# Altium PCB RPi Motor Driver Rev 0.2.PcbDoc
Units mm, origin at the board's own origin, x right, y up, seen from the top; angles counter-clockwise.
Board outline 65.25 x 56.75 mm, 2 copper layers (Top, Bottom); 42 components, 51 nets, 197 pads, 38 vias.
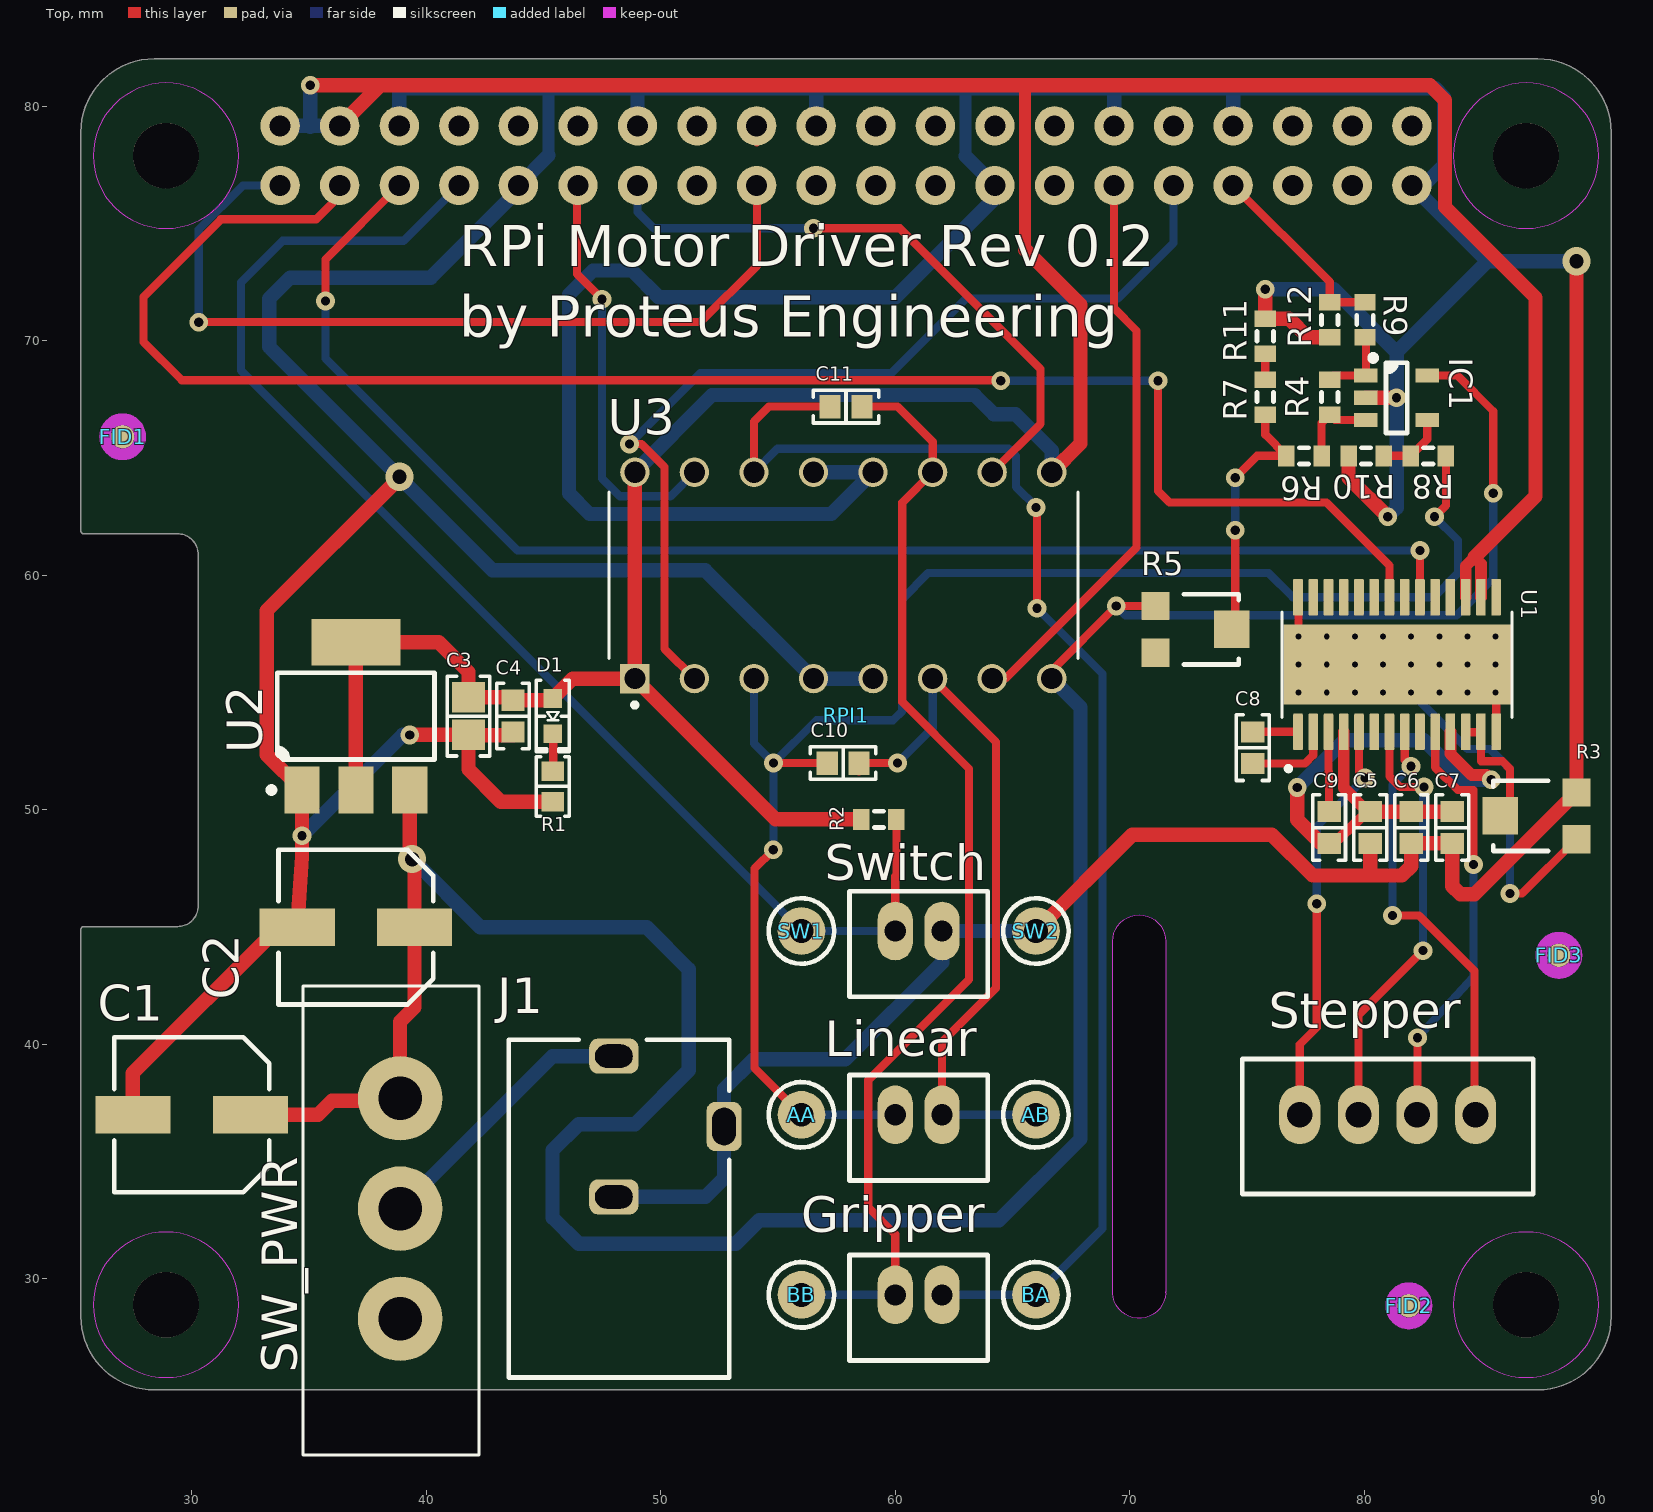
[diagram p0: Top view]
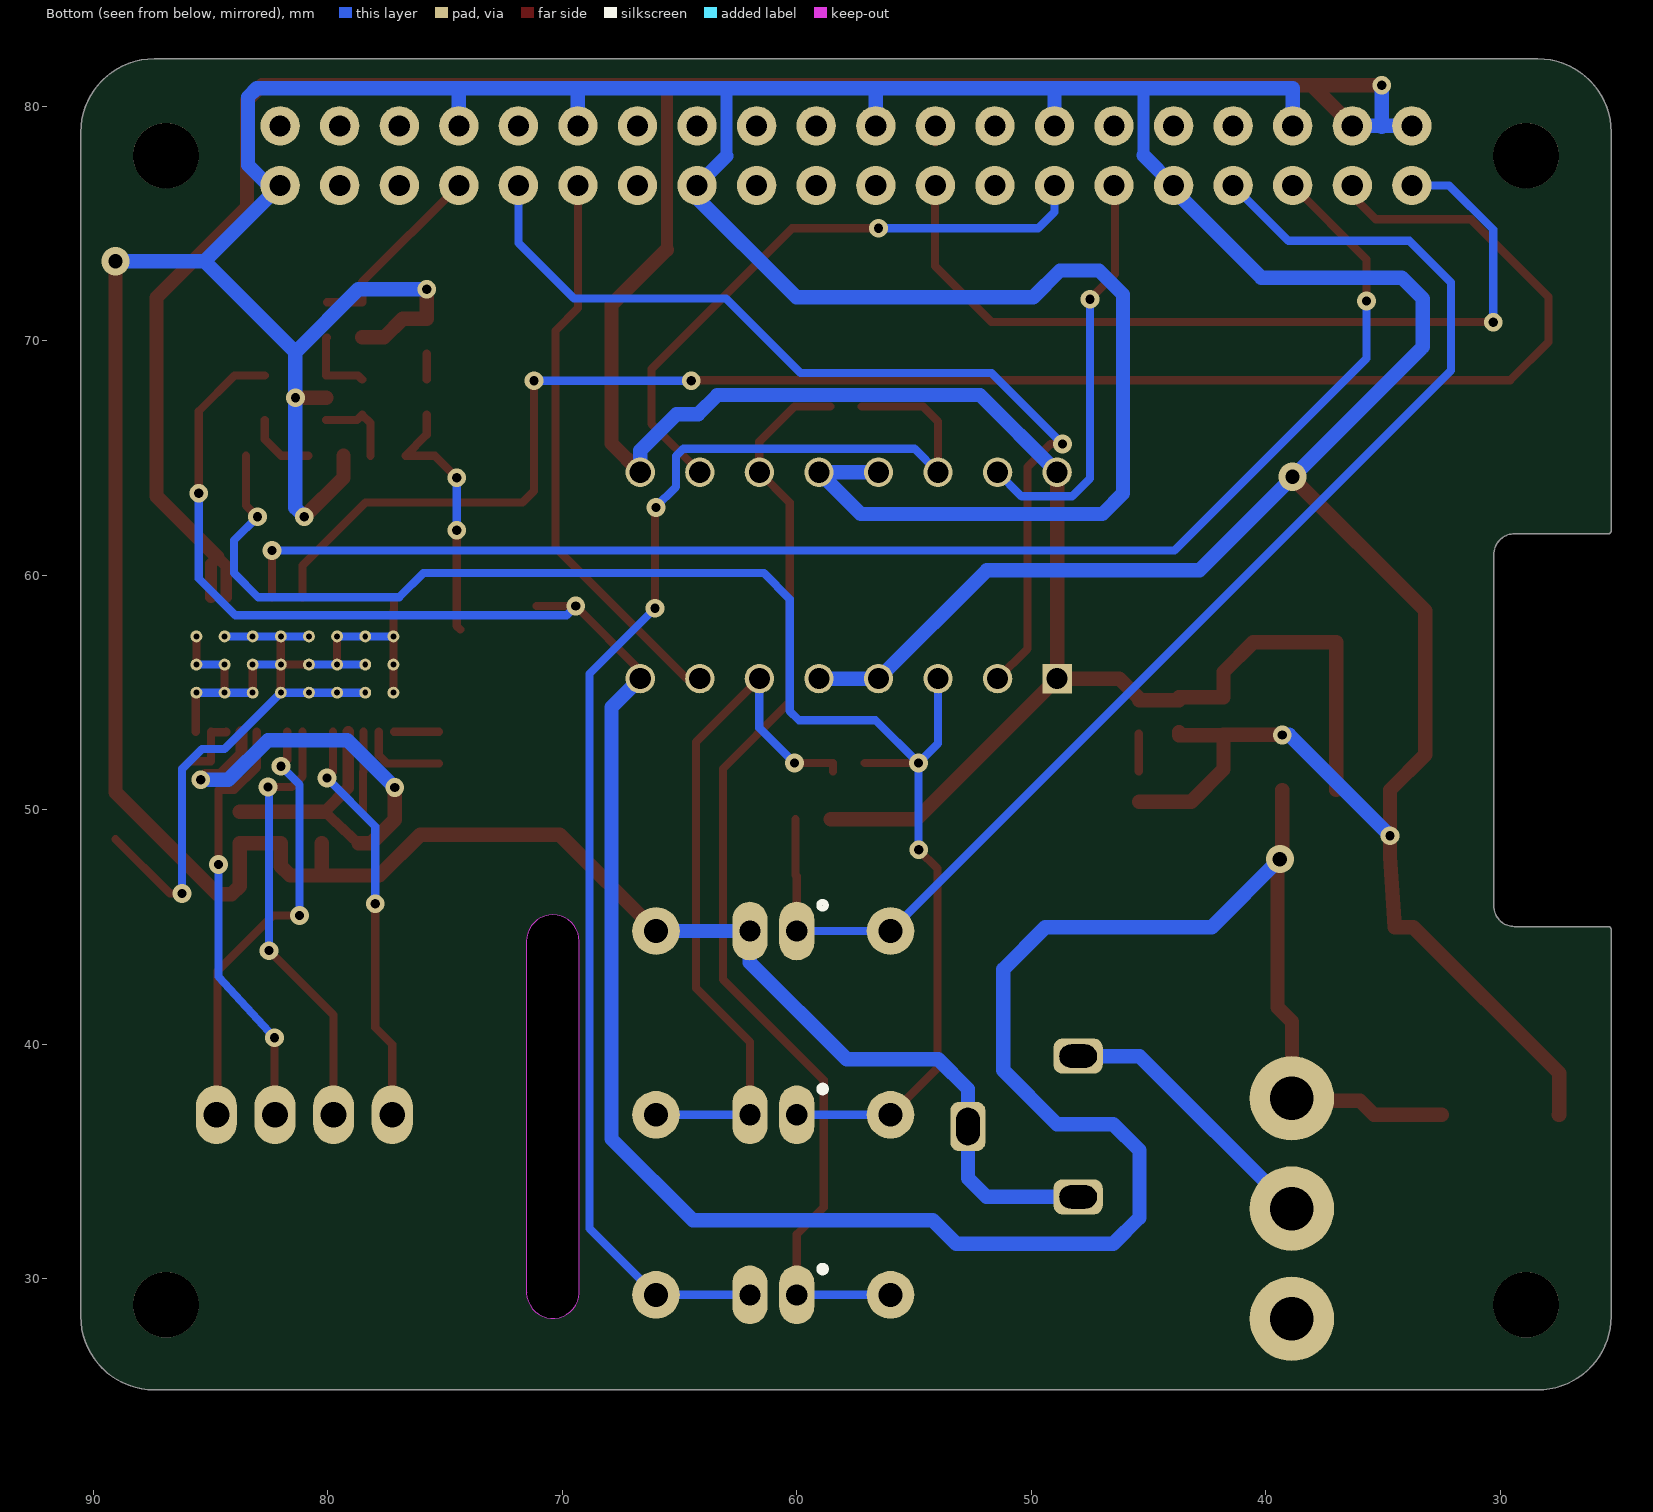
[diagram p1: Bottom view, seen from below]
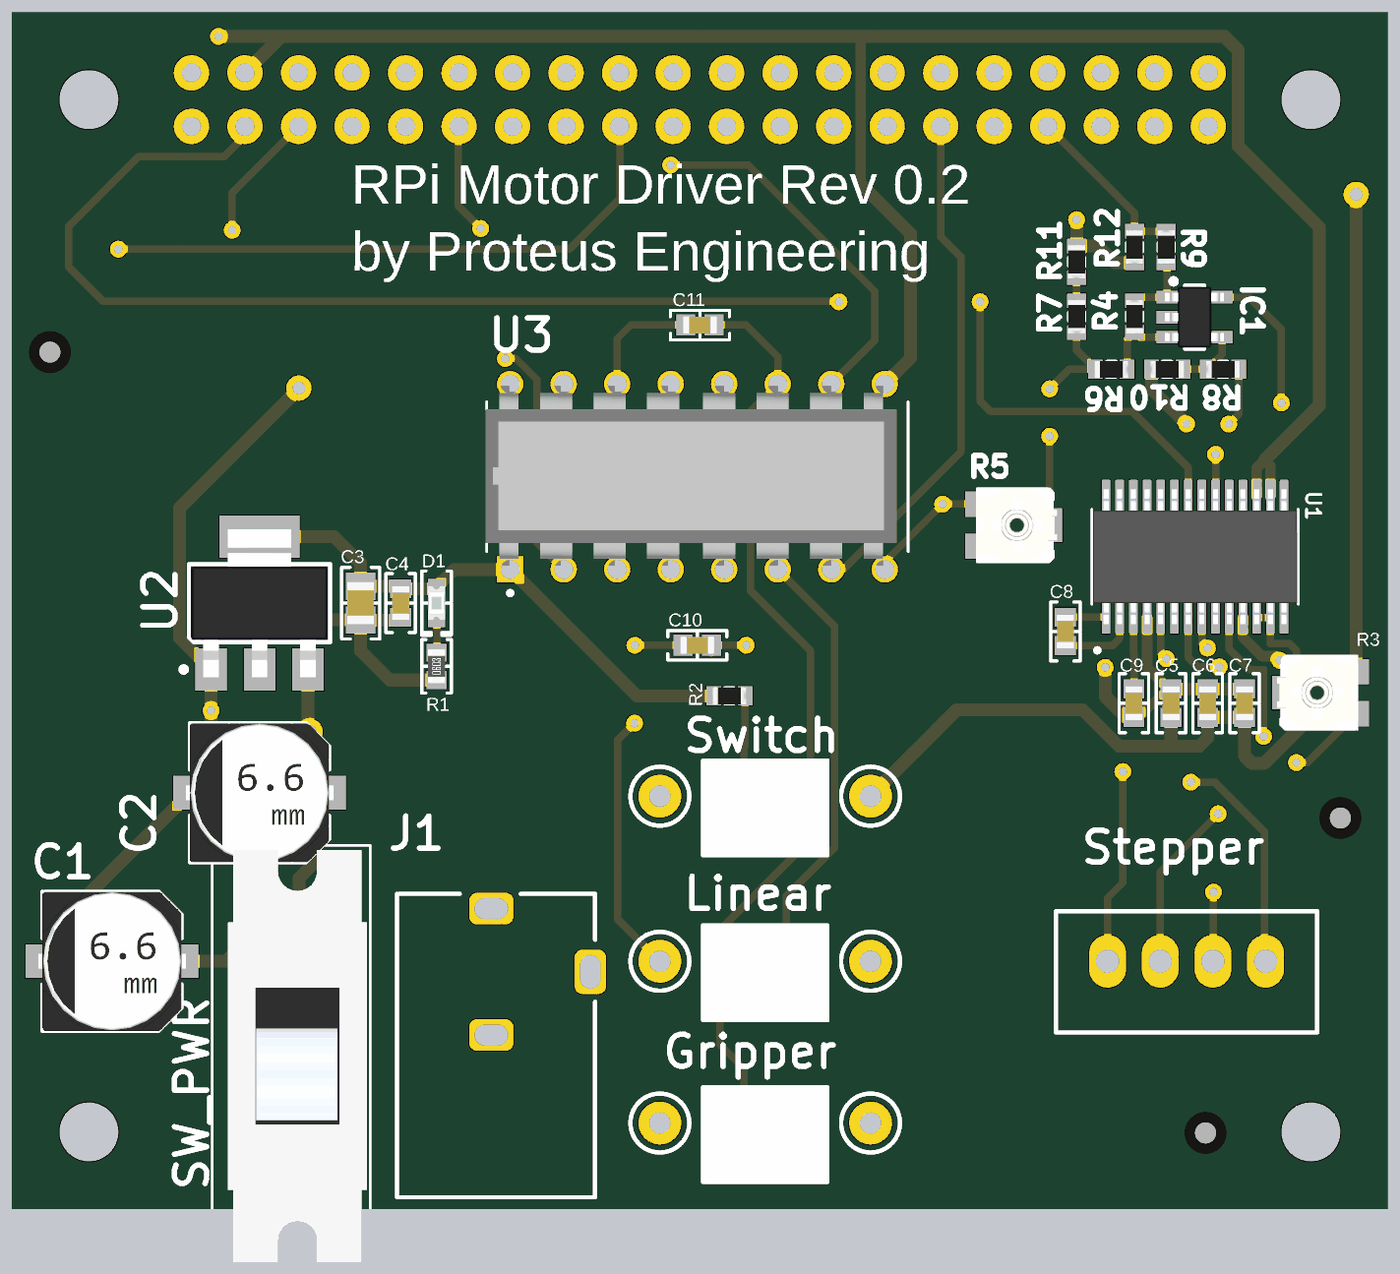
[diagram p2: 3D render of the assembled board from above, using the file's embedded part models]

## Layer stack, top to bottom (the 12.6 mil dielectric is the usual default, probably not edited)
Top Solder: solder mask 0.0102, Solder Resist, Dk 3.5
Top: signal copper 0.035
Dielectric 1: dielectric 0.32, FR-4, Dk 4.8
Bottom: signal copper 0.035
Bottom Solder: solder mask 0.0102, Solder Resist, Dk 3.5

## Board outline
25.273,28.4 25.273,44.9 cw(c25.4,44.9) 25.401,45.027 29.4,45.027 ccw(c29.4,45.9) 30.273,45.9 30.273,60.9 ccw(c29.4,60.9) 29.4,61.773 25.4,61.773 cw(c25.4,61.9) 25.273,61.9 25.273,78.9 cw(c28.4,78.9) 28.4,82.027 87.4,82.027 cw(c87.4,78.9) 90.528,78.9 90.528,28.4 cw(c87.4,28.4) 87.4,25.273 28.4,25.273 cw(c28.4,28.4)
cut-out: 69.277,29.432 cw(c69.4,29.464) 69.273,29.464 69.273,44.4 cw(c70.4,44.4) 71.527,44.4 71.527,29.464 cw(c71.4,29.464) 71.523,29.432 cw(c71.4,29.4) 71.527,29.4 cw(c71.4,29.4) 71.527,29.394 cw(c70.4,29.449) 69.273,29.394 cw(c69.4,29.4)

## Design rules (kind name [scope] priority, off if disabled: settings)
Clearance "Clearance (Same Net)" [All] p1: gap=0.203 ignorepadtopadclearanceinfootprint=FALSE
Clearance [All] p2: gap=0.152 ignorepadtopadclearanceinfootprint=FALSE
ComponentClearance [All] p1 off: gap=0.254 collisioncheckmode=3 verticalgap=0.254 showdistances=FALSE
HoleSize [All] p1: absolutevalues=TRUE maxlimit=2540 minlimit=0.254 maxpercent=80.000 minpercent=20.000
HoleToHoleClearance mdDrill [All] p1: gap=0.203 allowstackedmicrovias=TRUE
PasteMaskExpansion Expansion_SMDPaste_OFF [InPadClass('SMDPaste_OFF')] p1: expansion=0
PasteMaskExpansion mlMinCreamFrame [All] p2: expansion=0
PolygonConnect ThermalVias [IsVia] p1: connectstyle=Direct reliefconductorwidth=0.254 reliefentries=4 polygonreliefangle="90 Angle" airgapwidth=0.254
PolygonConnect [All] p2: connectstyle=Relief reliefconductorwidth=0.254 reliefentries=4 polygonreliefangle="90 Angle" airgapwidth=0.254
RoutingVias [All] p1: holewidth=0.394 width=0.8 viastyle="Through Hole" minholewidth=0.394 minwidth=0.8 maxholewidth=2.54 maxwidth=2.54
SolderMaskExpansion mlMinStopFrame [All] p1: expansion=0.051
Width [All] p1: maxlimit=0.7 minlimit=0.35 preferedwidth=0.35
26 further rules are at their usual default settings.

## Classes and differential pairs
pad class SMDPaste_OFF: FID1-1 FID2-1

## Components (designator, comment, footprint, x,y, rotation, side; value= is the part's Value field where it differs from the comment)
AA "TH_Testpoint_40mil" TH_Testpoint_40mil 56,37 r0 top
AB "TH_Testpoint_40mil" TH_Testpoint_40mil 66,37 r0 top
BA "TH_Testpoint_40mil" TH_Testpoint_40mil 66,29.322 r0 top
BB "TH_Testpoint_40mil" TH_Testpoint_40mil 56,29.322 r0 top
C1 "47µF" "CAP ALSMD 6.6MM H6.1MM" 30,37 r180 top
C2 "47µF" "CAP ALSMD 6.6MM H6.1MM" 37,45 r180 top
C3 "10µF" "CAP 0805_2012" 41.8,54 r90 top
C4 "0.1µF" "CAP 0603_1608" 43.7,54 r90 top
C5 "4.7µF" "CAP 0603_1608" 80.26,49.25 r90 top
C6 "0.1µF" "CAP 0603_1608" 82,49.25 r90 top
C7 "0.1µF" "CAP 0603_1608" 83.753,49.25 r90 top
C8 "0.01µF" "CAP 0603_1608" 75.25,52.655 r90 top
C9 "0.1µF" "CAP 0603_1608" 78.5,49.25 r90 top
C10 "0.1µF" "CAP 0603_1608" 57.775,52 r180 top
C11 "0.1µF" "CAP 0603_1608" 57.9,67.2 r180 top
D1 "Green" "LED 0603_1608 GREEN" 45.4,54 r270 top
FID1 "FIDUCIAL\"\"" FIDUCIAL_1MM 27.051,65.913 r0 top
FID2 "FIDUCIAL\"\"" FIDUCIAL_1MM 81.9,28.853 r0 top
FID3 "FIDUCIAL\"\"" FIDUCIAL_1MM 88.3,43.8 r0 top
Gripper "B2B-PH-K-S(LF)(SN)" "JST B2B-PH-K" 61,29.322 r0 top
IC1 "AD8615AUJZ-REEL" "ANALOG TSOT-23-5 UJ-5" 81.38,67.575 r0 top
Linear "B2B-PH-K-S(LF)(SN)" "JST B2B-PH-K" 61,37 r0 top
R1 "100 Ohms" "RES 0603_1608" 45.4,51 r90 top
R2 "Resistor 0603" 0603R 59.3,49.6 r180 top value=100k
R3 "10 kOhms" "POT BOURNS TRIMPOT TC33" 87.25,49.75 r90 top
R4 "Resistor 0603" 0603R 78.53,67.6 r270 top value=50k
R5 "200 Ohms" "POT BOURNS TRIMPOT TC33" 72.9,57.7 r270 top
R6 "Resistor 0603" 0603R 77.43,65.1 r180 top value=1k
R7 "Resistor 0603" 0603R 75.78,67.6 r90 top value=200
R8 "Resistor 0603" 0603R 82.73,65.1 r0 top value=1k
R9 "Resistor 0603" 0603R 80.03,70.9 r270 top value=470k
R10 "Resistor 0603" 0603R 80.08,65.1 r0 top value=50k
R11 "Resistor 0603" 0603R 75.78,70.2 r90 top value=470
R12 "Resistor 0603" 0603R 78.53,70.9 r90 top value=200k
RPI1 "RASPBERRYPI_BPLUS_HATSLOTS" PI_HAT_SLOTS 25.4,25.4 r0 top
SW1 "TH_Testpoint_40mil" TH_Testpoint_40mil 56,44.835 r0 top
SW2 "TH_Testpoint_40mil" TH_Testpoint_40mil 66,44.835 r0 top
SW_PWR "48ASSP3S1M2QBT" "SWITCH SLIDE SPDT 5A 125V" 36,33 r270 top
Switch "B2B-PH-K-S(LF)(SN)" "JST B2B-PH-K" 61,44.835 r0 top
U1 "DRV8825PWP" SOP65P640X120-29N 81.4,56.2 r90 top
U2 "NCP1117ST50T3G" "ON SEMI SOT-223 ST(318H)" 37,54 r90 top
U3 "L293D" DIP880W50P254L2000H510Q16 57.785,60 r90 top

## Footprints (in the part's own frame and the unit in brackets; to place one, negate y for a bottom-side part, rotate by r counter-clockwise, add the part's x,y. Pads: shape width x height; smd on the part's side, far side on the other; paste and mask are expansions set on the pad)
0603R [mm] "Resistor"
  rect 0.7x0.9 smd: 1(-0.75,0) 2(0.75,0)
  silkscreen extent -0.2,-0.35 0.2,0.35, body extent -0.8,-0.4 0.8,0.4, height 0.45
"ANALOG TSOT-23-5 UJ-5" [mm] "SOT23, 5-Leads, Body 2.90x1.60mm, Pitch 0.95mm, IPC Medium Density"
  rect 1x0.6 smd: 1(-1.31,0.95) 2(-1.31,0) 3(-1.31,-0.95) 4(1.31,-0.95) 5(1.31,0.95)
  silkscreen extent -1.12,-1.5 0.45,1.82, body extent -1.4,-1.45 1.4,1.45, height 1
"CAP 0603_1608" [mm] "Chip Capacitor, 2-Leads, Body 1.60x0.80mm, IPC Medium Density"
  rect 0.9x1 smd: 1(-0.675,0) 2(0.675,0)
  silkscreen extent -1.4,-0.7 1.4,0.7, body extent -0.8,-0.41 0.8,0.41, height 0.82
"CAP 0805_2012" [mm] "Chip Capacitor, 2-Leads, Body 2.00x1.20mm, IPC Medium Density"
  rect 1.3x1.4 smd: 1(-0.8,0) 2(0.8,0)
  silkscreen extent -1.7,-0.9 1.7,0.9, body extent -1,-0.64 1,0.64, height 1.26
"CAP ALSMD 6.6MM H6.1MM" [mm] "Aluminum Electrolytic Capacitor, Body 6.60x6.60x6.10mm, IPC Low Density"
  rect 3.2x1.6 smd: 1(-2.5,0) 2(2.5,0)
  silkscreen extent -3.3,-3.3 3.3,3.3, body extent -3.5,-3.3 3.5,3.3, height 6.1
DIP880W50P254L2000H510Q16 [mm]
  rect 1.25x1.25 hole 0.9: 1(-4.4,8.89)
  round 1.25 hole 0.9: 2(-4.4,6.35) 3(-4.4,3.81) 4(-4.4,1.27) 5(-4.4,-1.27) 6(-4.4,-3.81) 7(-4.4,-6.35) 8(-4.4,-8.89) 9(4.4,-8.89) 10(4.4,-6.35) 11(4.4,-3.81) 12(4.4,-1.27) 13(4.4,1.27) 14(4.4,3.81) 15(4.4,6.35) 16(4.4,8.89)
  silkscreen extent -5.62,-10 3.55,10, body extent -4.23,-9.45 4.3,10.05, height 3.09
FIDUCIAL_1MM [mm] "FIDUCIAL_1MM"
  rrect100% 1x1 smd paste+0: 1(0,0)
  Top keep-out lines w0.5: -0.75,0 ccw(c0,0) 0,-0.75 ccw(c0,0) 0.75,0 ccw(c0,0) 0,0.75 ccw(c0,0) -0.75,0
"JST B2B-PH-K" [mm]
  oval 1.5x2.5 hole 0.9: 1(-1,0) 2(1,0)
  silkscreen extent -2.95,-2.8 2.95,1.7, body extent -2.95,-2.8 2.95,1.7, height 6
"LED 0603_1608 GREEN" [mm] "Chip Diode, 2-Leads, Body 1.60x0.80mm, IPC Medium Density"
  rect 0.8x0.8 smd: 1(-0.75,0) 2(0.75,0)
  silkscreen extent -1.52,-0.7 1.52,0.7, body extent -0.8,-0.4 0.8,0.4, height 0.53
"ON SEMI SOT-223 ST(318H)" [mm] "SOT223, 4-Leads, Body 6.50x7.00mm (avg), Pitch 2.30mm, IPC Medium Density"
  rect 2x1.5 smd: 1(-3.15,2.3) 2(-3.15,0) 3(-3.15,-2.3)
  rect 2x3.8 smd: 4(3.15,0)
  silkscreen extent -3.27,-3.35 1.85,3.72, body extent -3.52,-3.25 3.5,3.25, height 1.8
PI_HAT_SLOTS [mil] "PI_HAT_SLOTS"
  round 110.24 hole 110.24 unplated: 1(137.8,137.8) 1(137.8,2066.93) 1(2421.26,137.8) 1(2421.26,2066.93)
  round 66 / inner round 60 / far side round 66 hole 35.43: 1(329.53,2016.93) 2(329.53,2116.93) 3(429.53,2016.93) 4(429.53,2116.93) 5(529.53,2016.93) 6(529.53,2116.93) 7(629.53,2016.93) 8(629.53,2116.93) 9(729.53,2016.93) 10(729.53,2116.93) 11(829.53,2016.93) 12(829.53,2116.93) 13(929.53,2016.93) 14(929.53,2116.93) 15(1029.53,2016.93) 16(1029.53,2116.93) 17(1129.53,2016.93) 18(1129.53,2116.93) 19(1229.53,2016.93) 20(1229.53,2116.93) 21(1329.53,2016.93) 22(1329.53,2116.93) 23(1429.53,2016.93) 24(1429.53,2116.93) 25(1529.53,2016.93) 26(1529.53,2116.93) 27(1629.53,2016.93) 28(1629.53,2116.93) 29(1729.53,2016.93) 30(1729.53,2116.93) 31(1829.53,2016.93) 32(1829.53,2116.93) 33(1929.53,2016.93) 34(1929.53,2116.93) 35(2029.53,2016.93) 36(2029.53,2116.93) 37(2129.53,2016.93) 38(2129.53,2116.93) 39(2229.53,2016.93) 40(2229.53,2116.93)
  Top keep-out circle w0: c137.8,137.8 r122.05
  Top keep-out circle w0: c2421.26,137.8 r122.05
  Top keep-out circle w0: c137.8,2066.93 r122.05
  Top keep-out circle w0: c2421.26,2066.93 r122.05
"POT BOURNS TRIMPOT TC33" [mm] "Bourns Trimpot TC33X-1 - Open Frame 3mm x 3.8mm x 1.2mm"
  rect 1.2x1.2 smd: 1(-1,-1.8) 3(1,-1.8)
  rect 1.6x1.5 smd: 2(0,1.45)
  silkscreen extent -1.5,-0.6 1.5,1.75, body extent -1.8,-1.91 1.8,1.95, height 1.15
"RES 0603_1608" [mm] "Chip Resistor, 2-Leads, Body 1.60x0.80mm, IPC Medium Density"
  rect 0.85x0.95 smd: 1(-0.65,0) 2(0.65,0)
  silkscreen extent -1.27,-0.7 1.27,0.7, body extent -0.8,-0.4 0.8,0.4, height 0.45
SOP65P640X120-29N [mm]
  rrect25% 1.57x0.41 smd: 1(-2.87,4.225) 2(-2.87,3.575) 3(-2.87,2.925) 4(-2.87,2.275) 5(-2.87,1.625) 6(-2.87,0.975) 7(-2.87,0.325) 8(-2.87,-0.325) 9(-2.87,-0.975) 10(-2.87,-1.625) 11(-2.87,-2.275) 12(-2.87,-2.925) 13(-2.87,-3.575) 14(-2.87,-4.225) 15(2.87,-4.225) 16(2.87,-3.575) 17(2.87,-2.925) 18(2.87,-2.275) 19(2.87,-1.625) 20(2.87,-0.975) 21(2.87,-0.325) 22(2.87,0.325) 23(2.87,0.975) 24(2.87,1.625) 25(2.87,2.275) 26(2.87,2.925) 27(2.87,3.575) 28(2.87,4.225)
  rect 3.4x9.7 smd paste-6 mask+0: 29(0,0)
  round 0.508 hole 0.254: P1(-1.2,0.6) P2(0,0.6) P3(1.2,0.6) P4(-1.2,-0.6) P5(0,-0.6) P6(1.2,-0.6) P7(-1.2,-1.8) P8(0,-1.8) P9(1.2,-1.8) P16(-1.2,1.8) P17(0,1.8) P18(1.2,1.8)
  round 0.508 hole 0.254 mask+0: P10(-1.2,-3) P11(0,-3) P12(1.2,-3) P13(-1.2,-4.2) P14(0,-4.2) P15(1.2,-4.2) P19(-1.2,3) P20(0,3) P21(1.2,3) P22(-1.2,4.2) P23(0,4.2) P24(1.2,4.2)
  silkscreen extent -4.54,-4.9 2.25,4.9, body extent -3.2,-4.85 3.2,4.85, height 1.18
"SWITCH SLIDE SPDT 5A 125V" [mm]
  round 3.6 hole 1.85 paste+0 mask+0.102: 1(-4.7,2.885) 2(0,2.885) 3(4.7,2.885)
  silkscreen extent -9.5,-1.25 10.5,6.25, body extent -9.28,-0.5 10.28,6.1, height 11.41
TH_Testpoint_40mil [mil]
  round 80 hole 40 paste-40: 1(0,0)
  silkscreen extent -55,-55 55,55

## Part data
AA AB BA BB SW1 SW2: "TH Testpoint"
C1 C2: library part UCD1V470MCL1GS, "CAP ALUM 47UF 20% 35V SMD", Device Package="Radial, Can - SMD", Lifetime @ Temp.="2000 Hrs @ 105°C", Manufacturer=Nichicon, Operating Temperature="-55°C ~ 105°C", Part Number=EEE-FP1V470AP, Ratings=AEC-Q200, Ripple Current @ High Frequency="240mA @ 100kHz", Ripple Current @ Low Frequency="120mA @ 120Hz", Supplier Part Number 1=493-6426-1-ND, Tolerance=±20%, Voltage - Rated=35V
C3: library part C2012X5R1E106K085AC, "CAP CER 10UF 25V X5R 0805", Device Package="0805 (2012 Metric)", Manufacturer="TDK Corporation", Operating Temperature="-55°C ~ 85°C", Supplier Part Number 1=445-14387-1-ND, Temperature Coefficient=X5R, Tolerance=±10%, Voltage - Rated=25V
C4 C6 C7 C9 C10 C11: library part CGA3E2X7R1H104K080AE, "CAP CER 0.1UF 50V X7R 0603", Device Package="0603 (1608 Metric)", Manufacturer="TDK Corporation", Operating Temperature="-55°C ~ 125°C", Ratings=AEC-Q200, Supplier Part Number 1=445-15957-1-ND, Temperature Coefficient=X7R, Tolerance=±10%, Voltage - Rated=50V
C5: library part C1608X5R1V475M080AC, "CAP CER 4.7UF 35V X5R 0603", Device Package="0603 (1608 Metric)", Manufacturer="TDK Corporation", Operating Temperature="-55°C ~ 85°C", Supplier Part Number 1=445-9042-1-ND, Temperature Coefficient=X5R, Tolerance=±20%, Voltage - Rated=35V
C8: library part C0603C103KARACAUTO, "CAP CER 0.01UF 250V X7R 0603", Device Package="0603 (1608 Metric)", Manufacturer=KEMET, Operating Temperature="-55°C ~ 125°C", Ratings=AEC-Q200, Supplier Part Number 1=399-17960-1-ND, Temperature Coefficient=X7R, Tolerance=±10%, Voltage - Rated=250V
D1: library part APHD1608LCGCK, "LED GREEN CLEAR 1608 SMD", Current - Test=2mA, Device Package="0603 (1608 Metric)", Lens Color=Colorless, Manufacturer=Kingbright, Millicandela Rating=5mcd, Part Number=APT1608CGCK, Supplier Device Package=1608, Supplier Part Number 1=754-2031-1-ND, Voltage - Forward (Vf) (Typ)=1.9V
FID1 FID2 FID3: "Fiducial Alignment PointsVarious fiducial points for machine vision alignment."
Gripper Linear Switch: "CONN HEADER VERT 2POS 2MM", Current Rating (Amps)=2A, Insulation Color=Natural, Manufacturer="JST Sales America Inc.", Material Flammability Rating="UL94 V-0", Operating Temperature="-25°C ~ 85°C", Supplier Part Number 1=455-1704-ND, Voltage Rating=100V
IC1: "IC OPAMP GP 1 CIRCUIT TSOT23-5", Current - Input Bias=0.2pA, Current - Output / Channel=150mA, Current - Supply=1.7mA, Device Package="SOT-23-5 Thin, TSOT-23-5", Manufacturer="Analog Devices Inc.", Operating Temperature="-40°C ~ 125°C", Supplier Device Package=TSOT-23-5, Supplier Part Number 1=AD8615AUJZ-REELTR-ND, Voltage - Input Offset=23µV, Voltage - Supply, Single/Dual (±)="2.7V ~ 5.5V, ±1.35V ~ 2.75V"
R1: library part RNCS0603BKE100R, "RES 100 OHM 0.1% 1/16W 0603", Device Package="0603 (1608 Metric)", Manufacturer="Stackpole Electronics Inc", Operating Temperature="-55°C ~ 155°C", Power (Watts)="0.063W, 1/16W", Ratings=AEC-Q200, Supplier Device Package=0603, Supplier Part Number 1=RNCS0603BKE100RCT-ND, Temperature Coefficient=±25ppm/°C, Tolerance=±0.1%
R2 R4 R6 R7 R8 R9 R10 R11 R12: library part Resistor
R3: library part TC33X-2-103E, "TRIMMER 10K OHM 0.1W J LEAD TOP", Manufacturer="Bourns Inc.", Power (Watts)="0.1W, 1/10W", Resistive Material=Cermet, Supplier Part Number 1=TC33X-103ECT-ND, Temperature Coefficient=±250ppm/°C, Tolerance=±25%
R5: library part TC33X-2-201E, "TRIMMER 200 OHM 0.1W J LEAD TOP", Manufacturer="Bourns Inc.", Power (Watts)="0.1W, 1/10W", Resistive Material=Cermet, Supplier Part Number 1=TC33X-2-201ECT-ND, Temperature Coefficient=±250ppm/°C, Tolerance=±25%
SW_PWR: library part "SWITCH SLIDE SPDT 5A 125V", "SWITCH SLIDE SPDT 5A 125V"
U1: "Bipolar Motor Driver Power MOSFET Logic 28-HTSSOP", Package="HTSSOP-28 Texas Instruments"
U2: "IC REG LINEAR 5V 1A SOT223", Current - Output=1A, Current - Quiescent (Iq)=10mA, Device Package="TO-261-4, TO-261AA", Manufacturer="ON Semiconductor", Operating Temperature="0°C ~ 125°C", Supplier Device Package=SOT-223, Supplier Part Number 1=NCP1117ST50T3GOSCT-ND, Voltage - Input (Max)=20V, Voltage - Output (Min/Fixed)=5V, Voltage Dropout (Max)="1.2V @ 800mA"
U3: "Bipolar Motor Driver Parallel 16-PowerDIP", Package="SOIC-20 STMicroelectronics"

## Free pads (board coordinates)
  rrect50% 2.1x1.5 hole 1 slot 1.6 at 0 deg: 1(48,39.5) 2(48,33.5)
  oval 1.75x2.5 hole 1.1: 1(77.25,37) 2(79.75,37) 3(82.25,37) 4(84.75,37)
  rrect50% 1.5x2.1 hole 1 slot 1.6 at 90 deg: 3(52.7,36.5)

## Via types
v1: diameter 0.8, hole 0.394, Top to Bottom, 35 vias
v2: diameter 1.2, hole 0.61, Top to Bottom, 2 vias
v3: diameter 1.2, hole 0.6, Top to Bottom, 1 vias

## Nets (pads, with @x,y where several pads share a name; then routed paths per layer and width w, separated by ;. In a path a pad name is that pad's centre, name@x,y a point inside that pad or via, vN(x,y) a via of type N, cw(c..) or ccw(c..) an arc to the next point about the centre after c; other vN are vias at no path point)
5V: C3.2 C4.2 D1.1 R2.2 RPI1.2 RPI1.4 U1.16 U1.17 U2.2 U2.4 U3.1 U3.9 U3.16 | length 161.7
  Top w0.5: 65.532,73.889 65.532,80.899 ; U1.17 84.325,60.403 84.7,60.778 84.975,60.503 U1.16
  Top w0.61: v1(35.052,80.899) 38.039,80.899 ; RPI1.4 38.039,80.899 ; U2.2 37,53.975 U2.4 40.53,57.15 41.8,55.88 C3.2 43.7,54.8 C4.2 45.4,54.675 D1.1 46.25,55.6 U3.1 ; U3.16 U3.1 ; R2.2 54.895,49.6 U3.1 ; 65.532,73.889 65.557,73.889 67.9,71.546 67.9,65.625 U3.9 ; 65.557,80.9 65.532,80.899 ; 84.7,60.778 87.3,63.378 87.3,71.847 83.439,75.708 83.439,80.264 82.804,80.899 65.532,80.899 ; 38.039,80.899 65.532,80.899
  Bottom w0.61: RPI1.2 35.052,79.17 ; v1(35.052,80.899) 35.052,79.17 ; RPI1.4 35.099,79.17 ; U3.16 52.186,67.691 63.384,67.691 64.207,66.868 65.132,66.868 66.675,65.325 U3.9 ; 35.052,79.17 35.052,79.123 35.099,79.17 ; 35.052,79.17 35.099,79.17
12V: C1.1 C2.1 IC1.5 R5.1 SW_PWR.1 U2.3 U3.8 | length 126.4
  Top w0.35: U3.8@66.675,55.951 v1(69.424,58.7) R5.1 ; IC1.5 83.975,68.525 85.5,67 v1(85.5,63.5)
  Top w0.61: C1.1 35.382,37 35.982,37.6 38.885,37.6 38.885,40.97 39.5,41.585 C2.1 39.5,47.803 39.3,48.003 U2.3
  Bottom w0.35: v1(69.424,58.7) 69.824,58.3 83.93,58.3 85.5,59.87 v1(85.5,63.5)
  Bottom w0.61: v2(39.4,47.903) 42.303,45 49.4,45 51.2,43.2 51.2,38.9 48.9,36.6 46.5,36.6 45.385,35.485 45.385,32.615 46.5,31.5 53.2,31.5 54.2,32.5 64.428,32.5 67.9,35.972 67.9,54.375 U3.8
A1: pad.1@77.25,37 U1.5 | length 17.6
  Top w0.35: pad.1@77.25,37 77.25,40 77.975,40.725 v1(77.975,46.004) ; U1.5 79.775,51.619 v1(80.035,51.359)
  Bottom w0.35: v1(77.975,46.004) 77.975,49.298 v1(80.035,51.359)
A2: pad.2@79.75,37 U1.7 | length 19.8
  Top w0.35: pad.2@79.975,36 79.75,36.225 79.75,37 79.75,41.25 v1(82.5,44) ; U1.7 81.075,51.435 81.532,50.978 v1(82.55,50.978)
  Bottom w0.35: v1(82.5,44) 82.5,50.928 v1(82.55,50.978)
B1: pad.3@82.25,37 U1.10 | length 18.3
  Top w0.35: pad.3@82.275,37 v1(82.275,40.283) ; U1.10 83.025,51.816 83.991,50.85 84.658,50.85 v1(84.658,47.676)
  Bottom w0.35: v1(82.275,40.283) 84.658,42.891 v1(84.658,47.676)
B2: pad.4 U1.8 | length 18.9
  Top w0.35: v1(81.2,45.5) 82.338,45.5 84.7,43.138 pad.4@84.7,37 ; U1.8 81.725,52.133 v1(81.991,51.867)
  Bottom w0.35: v1(81.2,45.5) 81.2,51.076 v1(81.991,51.867)
EECLK: RPI1.28 | length 0.2
  Top w0.35: RPI1.28@66.79,79.006 RPI1.28
EEDATA: RPI1.27
GND: C1.2 C2.2 C3.1 C4.1 C5.1 C6.1 C7.1 IC1.2 pad.2@48,33.5 pad.3@52.7,36.5 R1.1 R3.3 R10.1 R11.2 R12.1 RPI1.6 RPI1.9 RPI1.14 RPI1.20 RPI1.25 RPI1.30 RPI1.34 RPI1.39 SW2.1 Switch.2 U2.1 U3.4 U3.5 U3.12 U3.13 | length 327.2
  Top w0.61: C1.2 27.483,37 27.483,38.777 33.706,45 C2.2 34.7,48.003 U2.1 33.2,52.35 33.2,58.5 v3@38.887,64.187 ; v1@39.281,53.2 C3.1 C3.1@41.8,53.188 ; C4.1 43.7,53.188 C3.1@41.8,53.188 ; R1.1 43.18,50.35 41.8,51.73 C3.1@41.8,53.188 ; SW2.1 70.111,48.946 76.054,48.946 77.8,47.2 80.3,47.2 ; RPI1.34@74.41,78.752 RPI1.34 ; v1(75.78,72.2) R11.2 76.8,70.95 77.6,70.15 R12.1 ; R10.1 79.33,64.17 v1(81,62.5) ; IC1.2 v1(81.38,67.575) ; C5.1 80.26,47.24 80.3,47.2 ; v2(89.05,73.4) R3.3 84.7,46.4 84.1,46.4 83.753,46.747 C7.1 C6.1 82,47.6 81.6,47.2 80.3,47.2
  Bottom w0.35: 33.3,69.748 33.4,69.648
  Bottom w0.5: 45.212,77.912 45.212,80.645 ; 62.992,77.888 62.992,80.772
  Bottom w0.61: 33.3,69.748 33.3,71.8 34.2,72.7 40.188,72.7 43.93,76.442 RPI1.9 45.212,77.912 ; 33.4,69.648 42.824,60.223 51.892,60.223 U3.4 U3.5 ; v1(34.7,48.9) 39,53.2 v1(39.3,53.2) ; RPI1.6 38.85,80.772 45.339,80.772 ; 45.212,80.645 45.339,80.772 ; pad.2@48,33.5 51.91,33.5 52.7,34.29 52.7,36.5 52.7,38.1 53.97,39.37 57.872,39.37 62,43.497 Switch.2 63.983,44.835 SW2.1 ; RPI1.14 49.01,80.772 ; U3.13 U3.12 57.273,62.618 46.967,62.618 46.085,63.5 46.085,71.977 47.107,73 48.776,73 49.919,71.857 60.009,71.857 64.516,76.364 RPI1.25 62.992,77.888 ; RPI1.20 56.63,80.772 ; RPI1.30 69.342,79.17 69.342,80.772 ; RPI1.34 74.41,80.772 ; v1(75.78,72.2) 78.7,72.2 81.38,69.52 ; v1(81,62.5) 81.38,62.88 v1(81.38,67.575) 81.38,69.52 ; v2(89.05,73.4) 85.26,73.4 ; 45.339,80.772 49.01,80.772 ; 49.01,80.772 56.63,80.772 ; 56.63,80.772 62.992,80.772 69.342,80.772 ; 69.342,80.772 74.41,80.772 ; 74.41,80.772 83.028,80.772 83.4,80.4 83.4,77.5 82.53,76.63 RPI1.39 85.26,73.4 ; 81.38,69.52 85.26,73.4
  other v3: 38.866,64.208
GPIO12: RPI1.32
GPIO16: RPI1.36 | length 0.3
  Bottom w0.35: RPI1.36@76.95,78.855 RPI1.36
GPIO18: RPI1.12 | length 0.4
  Bottom w0.35: RPI1.12@46.47,78.728 RPI1.12
GPIO19: RPI1.35
GPIO20: RPI1.38
GPIO21: RPI1.40 | length 0.1
  Bottom w0.35: RPI1.40 RPI1.40@82.079,79.121
GPIO22: RPI1.15
GPIO23: RPI1.16 | length 0.3
  Bottom w0.35: RPI1.16@51.55,78.855 RPI1.16
GPIO24: RPI1.18 | length 0.7
  Top w0.35: RPI1.18@54.09,78.474 RPI1.18
GPIO25: RPI1.22 | length 0.1
  Top w0.35: RPI1.22@59.104,79.17 RPI1.22
GPIO26: RPI1.37
GRIPPER_COMPRESS: RPI1.11 U3.15 | length 17.7
  Top w0.35: RPI1.11 46.43,76.63 46.43,72.848 v1(47.498,71.78)
  Bottom w0.35: v1(47.498,71.78) 47.498,64.135 48.26,63.373 50.408,63.373 U3.15
GRIPPER_DECOMPRESS: RPI1.13 U3.10 | length 26.4
  Top w0.35: v1(56.515,74.8) 60.2,74.8 66.2,68.8 66.2,66.465 U3.10
  Bottom w0.35: RPI1.13 49.01,75.5 49.71,74.8 v1(56.515,74.8)
LINEAR_DRIVE_BACK: RPI1.31 U3.2 | length 40.7
  Top w0.35: v1(48.666,65.608) 49.174,65.608 50.165,64.618 50.165,56.87 U3.2
  Bottom w0.35: v1(48.666,65.608) 51.689,68.631 59.842,68.631 63.017,71.806 69.496,71.806 71.87,74.18 RPI1.31
LINEAR_DRIVE_FWD: RPI1.29 U3.7 | length 24.3
  Top w0.35: U3.7 64.7,55.6 70.293,61.193 70.293,70.434 69.33,71.398 RPI1.29
MOTOR_AA: AA.1 C10.2 Linear.1 R8.2 U3.3 | length 68.2
  Top w0.35: v1(54.8,48.3) 54,47.5 54,39 AA.1 ; v1(54.813,52) C10.2 ; v1(83,62.5) 83.48,62.98 R8.2
  Bottom w0.35: U3.3 53.975,52.838 v1(54.813,52) ; v1(54.8,48.3) 54.813,48.313 v1(54.813,52) ; AA.1 Linear.1 ; v1(83,62.5) 84,61.5 84,60.105 82.965,59.07 76.955,59.07 75.925,60.1 61.4,60.1 60.3,59 60.3,54.225 59.9,53.825 56.638,53.825 v1(54.813,52)
MOTOR_AB: AB.1 C10.1 Linear.2 U3.6 | length 31.4
  Top w0.35: C10.1@58.45,51.643 C10.1 v1(60.1,52) ; U3.6 64.3,52.895 64.3,42.4 62,40.1 Linear.2 Linear.2@62,36.5
  Bottom w0.35: v1(60.1,52) 61.595,53.495 U3.6 ; Linear.2 AB.1
MOTOR_BA: BA.1 C11.2 Gripper.2 U3.14 | length 59.9
  Top w0.35: U3.14 53.975,66.565 54.61,67.2 C11.2 ; v1(66,62.9) 66.04,62.86 v1(66.04,58.6)
  Bottom w0.35: U3.14 54.98,65.405 64.834,65.405 65.151,65.087 65.151,63.779 v1@66.04,62.89 ; Gripper.2 63.983,29.322 BA.1 68.834,32.156 68.834,55.806 v1(66.04,58.6)
MOTOR_BB: BB.1 C11.1 Gripper.1 U3.11 | length 48
  Top w0.35: C11.1 60.096,67.2 61.595,65.701 U3.11 60.3,63.105 60.3,54.6 63.144,51.756 63.144,42.774 58.852,38.481 58.852,33.051 60,31.902 Gripper.1
  Bottom w0.35: BB.1 57.988,29.322 Gripper.1
MOTOR_DIR: RPI1.5 U1.20 | length 60.7
  Top w0.35: v1(35.7,71.7) 35.7,73.48 RPI1.5 ; U1.20 v1(82.375,61.062)
  Bottom w0.35: v1(35.7,71.7) 35.7,69.253 43.891,61.062 v1(82.375,61.062)
MOTOR_STEP: RPI1.3 U1.22 | length 73.7
  Top w0.35: RPI1.3 36.31,76.188 35.306,75.184 31.242,75.184 27.94,71.882 27.94,69.96 29.574,68.326 v1@64.5,68.326 ; v1(71.2,68.303) 71.2,63.6 71.695,63.105 78.395,63.105 81.075,60.425 U1.22
  Bottom w0.35: v1(64.5,68.3) 71.197,68.3 v1(71.2,68.303)
NetC8_1: C8.1 U1.2 | length 3.7
  Top w0.35: C8.1 77.47,51.98 77.825,52.335 U1.2
NetC8_2: C8.2 U1.1 | length 1.9
  Top w0.35: C8.2 U1.1
NetC9_2: C9.2 U1.3 | length 3.4
  Top w0.35: U1.3 78.475,51.638 78.5,51.613 C9.2
NetD1_2: D1.2 R1.2 | length 1.6
  Top w0.35: R1.2 45.415,51.65 45.415,53.25 D1.2
NetIC1_1: IC1.1 R4.1 R9.2 | length 3.3
  Top w0.35: R4.1 78.705,68.525 IC1.1 80.07,70.11 R9.2
NetIC1_3: IC1.3 R4.2 R6.1 | length 3.5
  Top w0.35: R6.1 78.18,66.5 R4.2 78.755,66.625 IC1.3
NetIC1_4: IC1.4 R8.1 R10.2 | length 3
  Top w0.35: R10.2 R8.1 82.69,65.81 IC1.4
NetJ1_1: pad.1@48,39.5 SW_PWR.2 | length 11.8
  Bottom w0.61: SW_PWR.2 45.385,39.5 pad.1@48,39.5
NetR3_1: R3.1 U1.14 U1.28 U1.29 U1.P1 U1.P2 U1.P3 U1.P4 U1.P5 U1.P6 U1.P7 U1.P8 U1.P9 U1.P10 U1.P11 U1.P12 U1.P13 U1.P14 U1.P15 U1.P16 U1.P17 U1.P18 U1.P19 U1.P20 U1.P21 U1.P22 U1.P23 U1.P24 | length 45.7
  Top w0.35: U1.28 77.175,58.496 77.2,58.496 U1.P24 U1.P23 U1.P22 ; U1.P17 U1.P18 ; U1.P2 U1.29 U1.P5 ; U1.P4 U1.P5 ; U1.P6 U1.P5 ; U1.P7 83.2,55.575 U1.P8 ; U1.P10 U1.P11 ; U1.P13 85.625,54.975 U1.14 ; U1.P14 85.6,56.794 U1.P15 ; v1(86.215,46.431) 86.731,46.431 R3.1
  Bottom w0.35: U1.P24 U1.P21 U1.P18 ; U1.P19 U1.P16 U1.P1 U1.P4 84.4,52.6 85.367,52.6 86.215,51.752 v1(86.215,46.431) ; U1.P20 U1.P17 U1.P2 ; U1.P3 U1.P6 U1.P9 U1.P12 ; U1.P5 U1.P8 ; U1.P7 U1.P10 U1.P13 ; U1.P11 U1.P14
NetR5_2: R5.2 R6.2 R7.1 | length 11.2
  Top w0.35: R5.2 74.5,57.85 v1(74.5,61.925) ; v1(74.5,64.17) 75.43,65.1 R6.2 75.78,66 R7.1
  Bottom w0.35: v1(74.5,61.925) v1(74.5,64.17)
NetR7_2: R7.2 R11.1 | length 1.1
  Top w0.35: R7.2 R11.1
NetRPI1_1: RPI1.1@33.77,76.63 RPI1.17 | length 36.4
  Top w0.35: v1@30.3,70.804 51.704,70.804 54.1,73.2 54.1,76.62 RPI1.17
  Bottom w0.35: v1(30.3,70.8) 30.3,74.75 32.18,76.63 RPI1.1@33.77,76.63
SPI_CE0: RPI1.24 | length 0.3
  Top w0.35: RPI1.24@61.71,78.879 RPI1.24
SPI_CE1: RPI1.26 | length 0.2
  Bottom w0.35: RPI1.26@64.25,79.006 RPI1.26
SPI_MISO: RPI1.21
SPI_MOSI: RPI1.19
SPI_SCLK: RPI1.23
STALL_SIGNAL: R9.1 R12.2 RPI1.33 | length 8.3
  Top w0.35: RPI1.33 78.53,72.51 R12.2 R9.1
  Bottom w0.35: RPI1.33 RPI1.33@74.5,76.63
SWITCH_IN: R2.1 RPI1.7 SW1.1 Switch.1 | length 57.8
  Top w0.35: RPI1.7@41.39,76.188 RPI1.7 ; Switch.1 60,47.168 60.05,47.218 R2.1
  Bottom w0.35: RPI1.7 39.03,74.27 33.87,74.27 32.1,72.5 32.1,68.735 SW1.1 57.988,44.835 Switch.1
VMM: C5.2 C6.2 C7.2 C9.1 U1.4 U1.11 | length 25.7
  Top w0.45: C9.1@78.689,48.575 C5.2@80.137,49.925
  Top w0.5: U1.4 79.125,50.937 C5.2@80.137,49.925 ; U1.11 83.675,52.393 84.582,51.486 85.217,51.486 v1(85.42,51.283)
  Top w0.61: v1(77.14,50.952) 77.14,49.579 78.144,48.575 C9.1 C9.1@78.689,48.575 ; C5.2@80.137,49.925 C5.2 C6.2 C7.2
  Bottom w0.61: v1(77.14,50.952) 79.162,52.975 82.547,52.975 84.239,51.283 v1(85.42,51.283)
VREF: R3.2 U1.12 U1.13 | length 4.9
  Top w0.35: U1.12 84.325,53.315 U1.13@84.975,53.315 ; U1.13 U1.13@84.975,53.315 ; R3.2@86.215,50.1 86.215,51.752 85.892,52.075 84.975,52.075 U1.13@84.975,53.315
pads on no net: FID1.1 FID2.1 FID3.1 R5.3 RPI1.1@28.9,28.9 RPI1.1@28.9,77.9 RPI1.1@86.9,28.9 RPI1.1@86.9,77.9 RPI1.8 RPI1.10 SW_PWR.3 U1.6 U1.9 U1.15 U1.18 U1.19 U1.21 U1.23 U1.24 U1.25 U1.26 U1.27

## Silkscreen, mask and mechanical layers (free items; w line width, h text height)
Top Overlay:
  lines w0.2: 46.5,40.2 43.525,40.2 43.525,39.525 43.525,25.8 52.925,25.8 52.925,35.075 ; 49.4,40.2 52.925,40.2 52.925,38.025 ; 74.8,33.625 87.2,33.625 87.2,39.375 74.8,39.375 74.8,33.625
  text "RPi Motor Driver Rev 0.2 / by Proteus Engineering" at 41.4,69.6 h3
  text "J1" at 43.025,41.325 h1.52
  text "Stepper" at 75.925,40.7 h1.52
Dimension:
  lines w0.254: 69.4,29.4 ccw(c70.4,29.449) 71.4,29.4 ; 69.4,29.464 69.4,44.4 cw(c70.4,44.4) 71.4,44.4 71.4,29.464 ; 90.4,28.4 cw(c87.4,28.4) 87.4,25.4 28.4,25.4 cw(c28.4,28.4) 25.4,28.4 25.4,44.9 29.4,44.9 ccw(c29.4,45.9) 30.4,45.9 30.4,60.9 ccw(c29.4,60.9) 29.4,61.9 25.4,61.9 25.4,78.9 cw(c28.4,78.9) 28.4,81.9 87.4,81.9 cw(c87.4,78.9) 90.4,78.9 ; 90.4,29.6 90.4,80.1
Courtyard Top:
  lines w0.2: 80.5,37 81.5,37 ; 81,36.5 81,37.5 ; 74.3,33.1 87.7,33.1 87.7,39.9 74.3,39.9 74.3,33.1
  lines w0.254: 47.25,33 48,33 ; 48,32.25 48,33 ; 48,33.75 48,33 ; 48.75,33 48,33 ; 43,25.25 54,25.25 54,36.5 54,40.75 43,40.75 43,25.25

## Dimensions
25.527,30.607 to 78.105,29.083 on Courtyard Bottom
25.4,29.337 to 60.071,29.083 on Courtyard Bottom
25.4,29.591 to 41.402,29.083 on Courtyard Bottom
28.956,28.956 to 86.868,28.956 on Courtyard Bottom
28.829,77.851 to 28.956,28.956 on Courtyard Bottom
59.817,81.915 to 61.595,25.4 on Courtyard Bottom
25.527,65.913 to 90.424,61.468 on Courtyard Bottom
